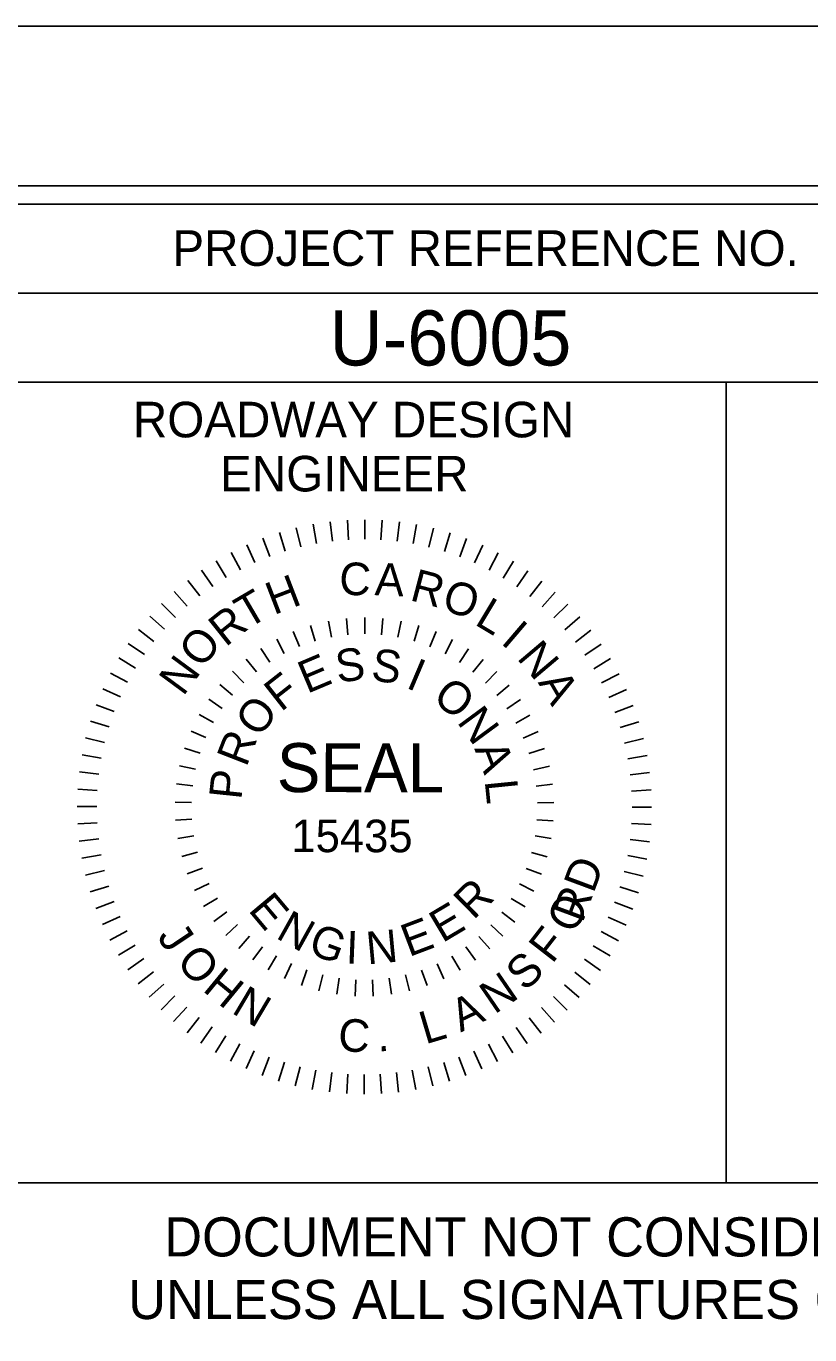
# Model space of a CAD drawing. Extents: x 1628636 to 1631253, y 896159 to 897520.
# Drawn here: x 1630528.1 to 1630638.2, y 897075 to 897258.9 of the extents above; entities that cross this region are included whole.
import ezdxf

# ---------------------------------------------------------------- set-up
doc = ezdxf.new("R2010")
doc.units = 0
for name, color, linetype in [('Old_Level_21', 7, 'Continuous'), ('Sheet Cutting Line CELL', 7, 'Continuous'), ('Sheet Data Field CELL', 7, 'Continuous'), ('Sheet Plot Border Inside CELL', 7, 'Continuous'), ('Sheet Plot Border Outside CELL', 7, 'Continuous'), ('Sheet Profile CELL', 7, 'Continuous'), ('Sheet Profile Grid Major CELL', 7, 'Continuous'), ('Sheet Profile Grid Minor CELL', 7, 'Continuous'), ('Sheet Sticker Exception Certification CELL', 7, 'Continuous')]:
    doc.layers.add(name, color=color, linetype=linetype)

msp = doc.modelspace()

# ---------------------------------------------------------------- linework, layer by layer
at = {"layer": 'Old_Level_21'}
for p, q in [((1630573.27, 897189.47), (1630573.43, 897186.73)), ((1630575.71, 897189.54), (1630575.71, 897186.79)), ((1630578.15, 897189.47), (1630577.98, 897186.72)), ((1630563.7, 897187.74), (1630564.51, 897185.1)), ((1630566.05, 897188.39), (1630566.7, 897185.71)), ((1630568.43, 897188.89), (1630568.92, 897186.19)), ((1630570.84, 897189.25), (1630571.17, 897186.52)), ((1630580.58, 897189.24), (1630580.24, 897186.51)), ((1630582.99, 897188.87), (1630582.49, 897186.17)), ((1630585.37, 897188.36), (1630584.71, 897185.69)), ((1630587.72, 897187.7), (1630586.9, 897185.07)), ((1630559.14, 897186.01), (1630560.26, 897183.5)), ((1630561.39, 897186.94), (1630562.37, 897184.37)), ((1630590.02, 897186.9), (1630589.04, 897184.33)), ((1630592.27, 897185.96), (1630591.14, 897183.46)), ((1630556.94, 897184.95), (1630558.22, 897182.51)), ((1630594.46, 897184.9), (1630593.18, 897182.46)), ((1630552.77, 897182.43), (1630554.33, 897180.16)), ((1630554.82, 897183.75), (1630556.24, 897181.4)), ((1630596.59, 897183.69), (1630595.16, 897181.34)), ((1630598.63, 897182.37), (1630597.07, 897180.11)), ((1630550.81, 897180.99), (1630552.5, 897178.82)), ((1630600.59, 897180.92), (1630598.89, 897178.76)), ((1630548.93, 897179.43), (1630550.75, 897177.37)), ((1630602.47, 897179.35), (1630600.64, 897177.3)), ((1630547.15, 897177.76), (1630549.09, 897175.81)), ((1630604.24, 897177.68), (1630602.29, 897175.74)), ((1630545.48, 897175.99), (1630547.53, 897174.16)), ((1630570.58, 897175.29), (1630571.01, 897173.04)), ((1630573.12, 897175.66), (1630573.34, 897173.38)), ((1630575.69, 897175.78), (1630575.69, 897173.49)), ((1630575.69, 897173.49), (1630575.69, 897175.78)), ((1630578.26, 897175.65), (1630578.04, 897173.37)), ((1630580.8, 897175.28), (1630580.36, 897173.03)), ((1630605.91, 897175.9), (1630603.84, 897174.08)), ((1630543.91, 897174.11), (1630546.07, 897172.42)), ((1630565.65, 897173.83), (1630566.52, 897171.71)), ((1630568.08, 897174.68), (1630568.73, 897172.48)), ((1630583.3, 897174.66), (1630582.64, 897172.46)), ((1630585.72, 897173.81), (1630584.85, 897171.68)), ((1630607.47, 897174.03), (1630605.3, 897172.33)), ((1630542.46, 897172.15), (1630544.73, 897170.59)), ((1630561.1, 897171.45), (1630562.36, 897169.53)), ((1630563.32, 897172.75), (1630564.38, 897170.72)), ((1630588.05, 897172.72), (1630586.99, 897170.69)), ((1630590.27, 897171.41), (1630589.01, 897169.49)), ((1630608.91, 897172.06), (1630606.64, 897170.5)), ((1630541.14, 897170.11), (1630543.49, 897168.68)), ((1630559.02, 897169.94), (1630560.46, 897168.15)), ((1630592.34, 897169.9), (1630590.9, 897168.11)), ((1630610.23, 897170.01), (1630607.87, 897168.59)), ((1630539.94, 897167.99), (1630542.37, 897166.7)), ((1630557.1, 897168.24), (1630558.7, 897166.6)), ((1630594.26, 897168.19), (1630592.66, 897166.55)), ((1630611.43, 897167.89), (1630608.98, 897166.61)), ((1630538.87, 897165.79), (1630541.37, 897164.66)), ((1630555.34, 897166.36), (1630557.09, 897164.88)), ((1630596.01, 897166.3), (1630594.26, 897164.83)), ((1630612.49, 897165.69), (1630609.98, 897164.57)), ((1630553.78, 897164.32), (1630555.66, 897163.01)), ((1630597.57, 897164.26), (1630595.68, 897162.96)), ((1630537.93, 897163.54), (1630540.5, 897162.56)), ((1630552.42, 897162.14), (1630554.42, 897161.02)), ((1630598.92, 897162.08), (1630596.92, 897160.96)), ((1630613.42, 897163.44), (1630610.84, 897162.46)), ((1630537.13, 897161.24), (1630539.76, 897160.42)), ((1630614.21, 897161.13), (1630611.58, 897160.32)), ((1630536.47, 897158.89), (1630539.14, 897158.23)), ((1630551.28, 897159.84), (1630553.38, 897158.92)), ((1630600.06, 897159.77), (1630597.96, 897158.85)), ((1630614.86, 897158.78), (1630612.19, 897158.13)), ((1630535.96, 897156.51), (1630538.66, 897156.01)), ((1630550.36, 897157.43), (1630552.55, 897156.72)), ((1630600.97, 897157.36), (1630598.78, 897156.66)), ((1630615.37, 897156.4), (1630612.66, 897155.91)), ((1630549.68, 897154.95), (1630551.92, 897154.46)), ((1630601.64, 897154.88), (1630599.4, 897154.39)), ((1630535.59, 897154.1), (1630538.32, 897153.76)), ((1630615.73, 897153.99), (1630613, 897153.66)), ((1630535.36, 897151.67), (1630538.11, 897151.5)), ((1630549.25, 897152.42), (1630551.52, 897152.14)), ((1630602.07, 897152.35), (1630599.79, 897152.08)), ((1630615.95, 897151.56), (1630613.2, 897151.4)), ((1630535.29, 897149.23), (1630538.04, 897149.23)), ((1630549.06, 897149.86), (1630551.35, 897149.8)), ((1630602.25, 897149.78), (1630599.96, 897149.73)), ((1630616.02, 897149.12), (1630613.27, 897149.12)), ((1630549.12, 897147.29), (1630551.4, 897147.45)), ((1630602.19, 897147.21), (1630599.9, 897147.38)), ((1630535.36, 897146.79), (1630538.1, 897146.95)), ((1630615.94, 897146.68), (1630613.2, 897146.85)), ((1630535.58, 897144.37), (1630538.31, 897144.69)), ((1630549.42, 897144.73), (1630551.68, 897145.12)), ((1630599.63, 897145.13), (1630601.89, 897144.75)), ((1630615.72, 897144.25), (1630612.99, 897144.59)), ((1630535.94, 897141.96), (1630538.64, 897142.45)), ((1630549.97, 897142.22), (1630552.18, 897142.82)), ((1630601.32, 897142.15), (1630599.11, 897142.75)), ((1630615.35, 897141.84), (1630612.65, 897142.34)), ((1630536.45, 897139.57), (1630539.12, 897140.22)), ((1630550.76, 897139.77), (1630552.91, 897140.58)), ((1630600.52, 897139.71), (1630598.38, 897140.52)), ((1630614.84, 897139.46), (1630612.17, 897140.12)), ((1630537.1, 897137.22), (1630539.73, 897138.03)), ((1630551.79, 897137.42), (1630553.84, 897138.43)), ((1630599.48, 897137.35), (1630597.43, 897138.37)), ((1630553.03, 897135.17), (1630554.98, 897136.37)), ((1630598.24, 897135.11), (1630596.29, 897136.32)), ((1630614.18, 897137.11), (1630611.55, 897137.93)), ((1630537.89, 897134.92), (1630540.46, 897135.89)), ((1630554.49, 897133.05), (1630556.32, 897134.44)), ((1630596.77, 897132.99), (1630594.95, 897134.39)), ((1630613.38, 897134.81), (1630610.81, 897135.79)), ((1630538.82, 897132.66), (1630541.33, 897133.78)), ((1630556.15, 897131.09), (1630557.83, 897132.64)), ((1630595.11, 897131.03), (1630593.44, 897132.59)), ((1630612.44, 897132.56), (1630609.93, 897133.69)), ((1630539.88, 897130.47), (1630542.32, 897131.74)), ((1630557.98, 897129.29), (1630559.51, 897131)), ((1630593.27, 897129.24), (1630591.75, 897130.96)), ((1630611.37, 897130.37), (1630608.94, 897131.65)), ((1630541.08, 897128.34), (1630543.43, 897129.76)), ((1630559.99, 897127.68), (1630561.34, 897129.53)), ((1630591.26, 897127.63), (1630589.92, 897129.49)), ((1630610.17, 897128.24), (1630607.82, 897129.67)), ((1630542.4, 897126.29), (1630544.67, 897127.85)), ((1630562.13, 897126.26), (1630563.3, 897128.24)), ((1630564.41, 897125.07), (1630565.38, 897127.15)), ((1630586.83, 897125.03), (1630585.87, 897127.12)), ((1630589.11, 897126.23), (1630587.95, 897128.21)), ((1630608.84, 897126.2), (1630606.58, 897127.76)), ((1630543.84, 897124.33), (1630546.01, 897126.02)), ((1630566.79, 897124.09), (1630567.56, 897126.26)), ((1630569.79, 897125.58), (1630569.23, 897123.35)), ((1630571.77, 897122.86), (1630572.11, 897125.12)), ((1630579.46, 897122.85), (1630579.13, 897125.11)), ((1630581.98, 897123.34), (1630581.44, 897125.57)), ((1630584.45, 897124.07), (1630583.69, 897126.23)), ((1630607.4, 897124.24), (1630605.23, 897125.94)), ((1630545.4, 897122.45), (1630547.46, 897124.27)), ((1630574.33, 897122.6), (1630574.44, 897124.89)), ((1630576.9, 897122.6), (1630576.8, 897124.89)), ((1630605.83, 897122.37), (1630603.78, 897124.19)), ((1630547.07, 897120.67), (1630549.02, 897122.61)), ((1630604.16, 897120.59), (1630602.22, 897122.54)), ((1630548.84, 897119), (1630550.67, 897121.05)), ((1630550.72, 897117.43), (1630552.41, 897119.6)), ((1630602.38, 897118.93), (1630600.56, 897120.99)), ((1630552.68, 897115.99), (1630554.24, 897118.25)), ((1630598.54, 897115.92), (1630596.98, 897118.19)), ((1630600.5, 897117.36), (1630598.81, 897119.53)), ((1630554.72, 897114.66), (1630556.15, 897117.01)), ((1630556.84, 897113.46), (1630558.13, 897115.89)), ((1630596.49, 897114.6), (1630595.07, 897116.96)), ((1630559.04, 897112.39), (1630560.17, 897114.9)), ((1630592.17, 897112.35), (1630591.05, 897114.85)), ((1630594.36, 897113.41), (1630593.09, 897115.85)), ((1630561.29, 897111.45), (1630562.27, 897114.02)), ((1630563.59, 897110.65), (1630564.41, 897113.28)), ((1630565.94, 897109.99), (1630566.6, 897112.66)), ((1630585.26, 897109.97), (1630584.61, 897112.64)), ((1630587.61, 897110.62), (1630586.8, 897113.25)), ((1630589.92, 897111.41), (1630588.94, 897113.99)), ((1630568.32, 897109.48), (1630568.82, 897112.18)), ((1630570.73, 897109.11), (1630571.07, 897111.84)), ((1630573.16, 897108.89), (1630573.33, 897111.63)), ((1630575.6, 897108.81), (1630575.6, 897111.56)), ((1630578.04, 897108.88), (1630577.88, 897111.63)), ((1630580.46, 897109.1), (1630580.14, 897111.83)), ((1630582.87, 897109.46), (1630582.38, 897112.17))]:
    msp.add_line(p, q, dxfattribs=at)
at = {"layer": 'Sheet Cutting Line CELL'}
msp.add_line((1630743.5, 897258.9), (1629059.5, 897258.9), dxfattribs=at)
at = {"layer": 'Sheet Plot Border Inside CELL'}
msp.add_lwpolyline([(1629072.5, 896181.35), (1630739, 896181.35), (1630739, 897236.45), (1629072.5, 897236.45)], close=True, dxfattribs=at)
at = {"layer": 'Sheet Plot Border Outside CELL'}
msp.add_lwpolyline([(1629059.5, 896158.9), (1630743.5, 896158.9), (1630743.5, 897258.9), (1629059.5, 897258.9)], close=True, dxfattribs=at)
at = {"layer": 'Sheet Profile CELL'}
for p, q in [((1630526.45, 897221.35), (1630726.5, 897221.35)), ((1630626.5, 897208.85), (1630626.5, 897096.4))]:
    msp.add_line(p, q, dxfattribs=at)
for points in [[(1630726.5, 897233.9), (1629226.5, 897233.9), (1629226.5, 896183.9), (1630726.5, 896183.9)], [(1630526.45, 897233.9), (1630726.5, 897233.9), (1630726.5, 897208.85), (1630526.45, 897208.85)], [(1630526.45, 897208.85), (1630626.5, 897208.85), (1630626.5, 897096.35), (1630526.45, 897096.35)], [(1630626.5, 897208.85), (1630726.5, 897208.85), (1630726.5, 897096.35), (1630626.5, 897096.35)]]:
    msp.add_lwpolyline(points, close=True, dxfattribs=at)
at = {"layer": 'Sheet Profile Grid Major CELL'}
msp.add_lwpolyline([(1630126.5, 897095.37), (1630126.5, 897233.9), (1630176.5, 897233.9), (1630176.5, 896733.9), (1630226.5, 896733.9), (1630226.5, 897233.9), (1630276.5, 897233.9), (1630276.5, 896733.9), (1630326.5, 896733.9), (1630326.5, 897233.9), (1630376.5, 897233.9), (1630376.5, 896733.9), (1630426.5, 896733.9), (1630426.5, 897233.9), (1630476.5, 897233.9), (1630476.5, 896733.9), (1630526.5, 896733.9), (1630526.5, 897233.9), (1630552.8, 897233.9)], dxfattribs=at)
at = {"layer": 'Sheet Profile Grid Minor CELL'}
msp.add_lwpolyline([(1630521.5, 897233.9), (1630531.5, 897233.9)], dxfattribs=at)
at = {"layer": 'Sheet Sticker Exception Certification CELL'}
msp.add_line((1630526.45, 897096.35), (1630726.49, 897096.35), dxfattribs=at)
msp.add_line((1630526.45, 897096.35), (1630726.49, 897096.35), dxfattribs=at)

# ---------------------------------------------------------------- texts
at = {"layer": 'Old_Level_21'}
for s, height, rotation, p in [('C', 4.58, 357.2771, (1630572.03, 897179.04)), ('A', 4.58, 357.2771, (1630577.04, 897178.94)), ('R', 4.58, 345.2678, (1630581.89, 897178.26)), ('H', 4.58, 20.9878, (1630562.91, 897176.11)), ('O', 4.58, 342.211, (1630586.33, 897176.94)), ('T', 4.58, 30.4198, (1630559.21, 897174.12)), ('L', 4.58, 329.0747, (1630590.99, 897174.89)), ('R', 4.58, 38.5807, (1630556.13, 897171.56)), ('I', 4.58, 319.4993, (1630594.68, 897172.22)), ('O', 4.58, 51.6375, (1630552.81, 897168.48)), ('S', 4.58, 7.5683, (1630571.9, 897166.61)), ('S', 4.58, 352.272, (1630576.47, 897166.98)), ('N', 4.58, 310.2048, (1630596.97, 897170.06)), ('N', 4.58, 53.5969, (1630550.17, 897164.61)), ('E', 4.58, 22.8645, (1630567.59, 897165.04)), ('I', 4.58, 336.9758, (1630581.34, 897165.98)), ('F', 4.58, 38.1608, (1630563.92, 897162.45)), ('A', 4.58, 300.4373, (1630599.99, 897166.67)), ('O', 4.58, 321.6795, (1630585.04, 897164.19)), ('O', 4.58, 53.457, (1630560.87, 897158.76)), ('N', 4.58, 306.3833, (1630588.56, 897161.12)), ('R', 4.58, 68.7533, (1630559.05, 897154.65)), ('SEAL', 6.878, 359.9202, (1630563.33, 897151.26)), ('A', 4.58, 291.0871, (1630591.07, 897157.36)), ('P', 4.58, 84.0495, (1630558.35, 897150.1)), ('L', 4.58, 275.7908, (1630592.55, 897152.83)), ('15435', 4.582, 359.9202, (1630565.38, 897142.82)), (' RD', 4.582, 69.5926, (1630605.7, 897131.17)), ('R', 4.58, 44.4851, (1630590.98, 897133.19)), ('E', 4.58, 309.9903, (1630559.21, 897134.65)), ('O ', 4.582, 60.9198, (1630605.03, 897131.15)), ('N', 4.58, 330.8453, (1630563.05, 897130.82)), ('E', 4.58, 30.714, (1630586.61, 897130)), ('J', 4.58, 303.8552, (1630546.42, 897130.92)), ('G', 4.58, 339.6116, (1630567.54, 897128.67)), ('E', 4.58, 20.7281, (1630581.91, 897128.05)), ('F', 4.58, 52.1272, (1630602.04, 897127.01)), ('I', 4.58, 357.7064, (1630572.99, 897127.19)), ('N', 4.58, 5.336, (1630576.1, 897127.03)), ('O', 4.58, 311.927, (1630549.04, 897127.27)), ('S', 4.58, 43.2446, (1630598.22, 897123.13)), ('H', 4.58, 320.5697, (1630552.77, 897123.4)), ('N', 4.58, 34.362, (1630593.93, 897119.95)), ('N', 4.58, 329.2423, (1630556.83, 897120.3)), ('A', 4.58, 25.5393, (1630589.17, 897117.46)), ('L', 4.58, 16.5368, (1630584.21, 897115.79)), ('C', 4.58, 356.0101, (1630571.85, 897114.92)), ('.', 4.58, 3.7525, (1630577.54, 897114.79))]:
    msp.add_text(s, height=height, rotation=rotation, dxfattribs=at).set_placement(p)
at = {"layer": 'Sheet Data Field CELL'}
msp.add_text('U-6005', height=7.75, dxfattribs=at).set_placement((1630570.74, 897211.21))
at = {"layer": 'Sheet Profile CELL'}
for s, height, p in [('PROJECT REFERENCE NO.', 5.0001, (1630548.66, 897225.21)), ('ROADWAY DESIGN', 5.0001, (1630543.11, 897201.11)), ('ENGINEER', 5, (1630555.36, 897193.51))]:
    msp.add_text(s, height=height, dxfattribs=at).set_placement(p)
at = {"layer": 'Sheet Sticker Exception Certification CELL'}
for s, p in [('DOCUMENT NOT CONSIDERED FINAL', (1630547.52, 897086)), ('DOCUMENT NOT CONSIDERED FINAL', (1630547.52, 897086)), ('UNLESS ALL SIGNATURES COMPLETED', (1630542.45, 897077.2)), ('UNLESS ALL SIGNATURES COMPLETED', (1630542.45, 897077.2))]:
    msp.add_text(s, height=5.5, dxfattribs=at).set_placement(p)

doc.saveas('drawing.dxf')
